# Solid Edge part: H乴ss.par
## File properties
Author: Türk
Template: Iso Part.par
Last saved by: Türk
Revision: 11
Application: Solid Edge
Accuracy: 0,990
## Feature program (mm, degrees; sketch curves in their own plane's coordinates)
pattern "PatternOccurrence_3"  XOffset = 30 deg
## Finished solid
Body 1: solid body, 52 faces, 148 edges, 96 vertices.
  Faces by surface: cylinder 26, plane 26
  Edges by curve: circle 100, line 48
Bounding box of the edges (mm): 40.500 x 50.000 x 40.500, from (-20.25, -5, -20.25) to (20.25, 45, 20.25).
Cylindrical faces by radius (mm): R4 x24, R16.75 x1, R20.25 x1
Planar faces by outward normal: +y 13, -y 13
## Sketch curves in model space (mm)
circle centre (0, -5, 0) radius 18.5
circle centre (0, -5, 0) radius 15
circle centre (0, -5, 0) radius 22
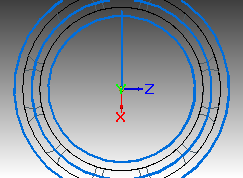
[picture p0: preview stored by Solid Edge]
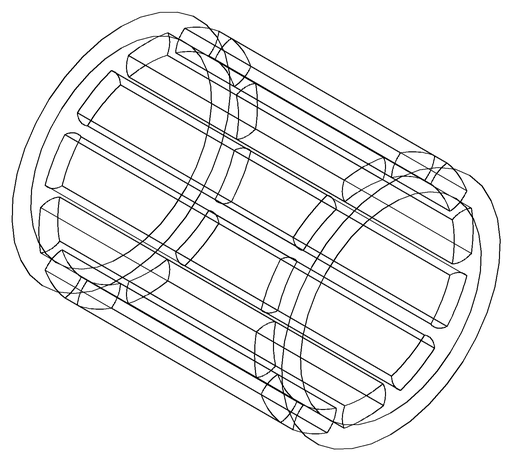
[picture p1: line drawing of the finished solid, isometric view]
